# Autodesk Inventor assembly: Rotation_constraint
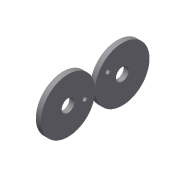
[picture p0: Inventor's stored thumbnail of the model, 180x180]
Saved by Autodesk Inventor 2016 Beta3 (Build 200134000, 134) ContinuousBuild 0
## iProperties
Created: 2016-03
Part Number: Rotation_constraint
Document SubType Name: Assembly
Designer: Gaurav
Author: Gaurav
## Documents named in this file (2)
- D:\My Data\Books_Final Books\Autodesk Inventor 2015_resources\Chapter 7\Wheel_motion\Rotation_constraint.iam
- D:\My Data\Books_Final Books\Autodesk Inventor 2015_resources\Chapter 7\Wheel_motion\wheel.ipt
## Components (2 placed, 1 different names)
1. wheel:1 — Tangent:1, Mate:1, Flush:1, Mate:4, Rotation:1
2. wheel:2 — Tangent:1, Mate:2, Flush:1, Mate:3, Rotation:1
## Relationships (7: Mate 4, Tangent 1, Flush 1, RelateRotation 1)
- Tangent:1: wheel:1 ↔ wheel:2
- Mate:1: wheel:1
- Mate:2: wheel:2
- Flush:1: wheel:1 ↔ wheel:2
- Mate:3: wheel:2
- Mate:4: wheel:1
- Rotation:1 [RelateRotation]: wheel:1 ↔ wheel:2
